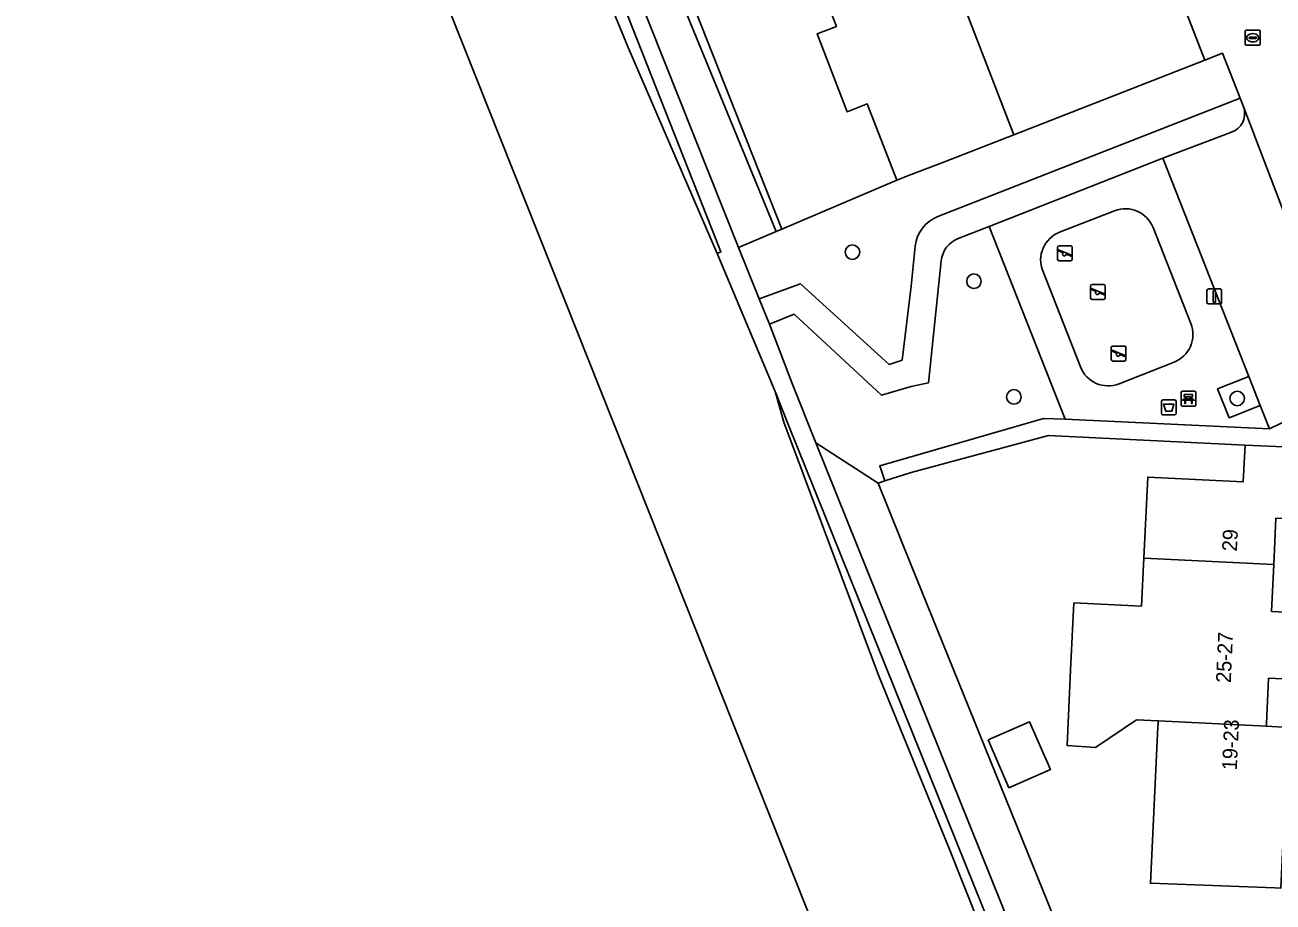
# Model space of a CAD drawing. Extents: x 158472 to 159562, y 388525 to 389606.
# Drawn here: x 158940.4 to 159024.3, y 388560.1 to 388619.1 of the extents above; entities that cross this region are included whole.
import ezdxf

# ---------------------------------------------------------------- set-up
doc = ezdxf.new("R2010")
doc.units = 0
for name, color, linetype in [('IMGEO_Afvalbak', 7, 'Continuous'), ('IMGEO_Bank', 7, 'Continuous'), ('IMGEO_Boom', 7, 'Continuous'), ('IMGEO_Erf', 7, 'Continuous'), ('IMGEO_Grasland_overig', 7, 'Continuous'), ('IMGEO_Groenvoorziening', 7, 'Continuous'), ('IMGEO_Hek', 7, 'Continuous'), ('IMGEO_Kolk', 7, 'Continuous'), ('IMGEO_Lichtmast', 7, 'Continuous'), ('IMGEO_Meer_plas_ven_vijver', 7, 'Continuous'), ('IMGEO_Oever', 7, 'Continuous'), ('IMGEO_Pand', 7, 'Continuous'), ('IMGEO_Pand_nummerreeks', 7, 'Continuous'), ('IMGEO_Parkeervlak_open', 7, 'Continuous'), ('IMGEO_Rijbaan_lokaal_open', 7, 'Continuous'), ('IMGEO_Speelvoorziening', 7, 'Continuous'), ('IMGEO_Terreindeel_zand', 7, 'Continuous'), ('IMGEO_Voetpad_halfverhard', 7, 'Continuous'), ('IMGEO_Voetpad_open', 7, 'Continuous'), ('IMGEO_Walbescherming', 7, 'Continuous')]:
    doc.layers.add(name, color=color, linetype=linetype)

msp = doc.modelspace()

# ---------------------------------------------------------------- linework, layer by layer
at = {"layer": 'IMGEO_Afvalbak'}
for p, q in [((159016.827, 388592.973), (159016.827, 388593.773)), ((159016.827, 388593.773), (159016.827, 388592.973)), ((159016.927, 388593.873), (159017.717, 388593.873)), ((159017.717, 388593.873), (159016.927, 388593.873)), ((159017.817, 388593.773), (159017.817, 388592.973)), ((159017.817, 388592.973), (159017.817, 388593.773)), ((159017.717, 388592.873), (159016.927, 388592.873)), ((159016.927, 388592.873), (159017.717, 388592.873))]:
    msp.add_line(p, q, dxfattribs=at)
msp.add_lwpolyline([(159016.97, 388593.587), (159017.674, 388593.587), (159017.525, 388593.117), (159017.119, 388593.117), (159016.97, 388593.587)], dxfattribs=at)
for centre, start, end in [((159016.927, 388593.773), 90, 180), ((159016.927, 388593.773), 90, 180), ((159017.717, 388593.773), 0, 90), ((159017.717, 388593.773), 360, 90), ((159016.927, 388592.973), 180, 270), ((159016.927, 388592.973), 180, 270), ((159017.717, 388592.973), 270, 0), ((159017.717, 388592.973), 270, 0)]:
    msp.add_arc(centre, 0.1, start, end, dxfattribs=at)
at = {"layer": 'IMGEO_Bank'}
for p, q in [((159018.147, 388593.529), (159018.147, 388594.37)), ((159018.147, 388594.37), (159018.147, 388593.529)), ((159018.222, 388594.454), (159019.063, 388594.454)), ((159019.063, 388594.454), (159018.222, 388594.454)), ((159018.456, 388593.96), (159018.456, 388594.066)), ((159018.5, 388594.066), (159018.5, 388593.96)), ((159018.788, 388594.072), (159018.506, 388594.072)), ((159018.506, 388593.954), (159018.788, 388593.954)), ((159018.794, 388593.96), (159018.794, 388594.066)), ((159018.838, 388594.066), (159018.838, 388593.96)), ((159019.147, 388594.379), (159019.147, 388593.538)), ((159019.147, 388593.538), (159019.147, 388594.379)), ((159019.072, 388593.454), (159018.231, 388593.454)), ((159018.231, 388593.454), (159019.072, 388593.454)), ((159018.844, 388593.852), (159018.451, 388593.852))]:
    msp.add_line(p, q, dxfattribs=at)
for points in [[(159018.394, 388593.852), (159018.252, 388593.852), (159018.364, 388593.954), (159018.45, 388593.954)], [(159018.45, 388594.072), (159018.364, 388594.072), (159018.364, 388594.233), (159018.927, 388594.233), (159018.927, 388594.072), (159018.844, 388594.072)], [(159018.844, 388593.954), (159018.927, 388593.954), (159019.039, 388593.852), (159018.9, 388593.852)], [(159018.444, 388593.845), (159018.444, 388593.638), (159018.401, 388593.638), (159018.401, 388593.845)], [(159018.894, 388593.845), (159018.894, 388593.638), (159018.85, 388593.638), (159018.85, 388593.845)]]:
    msp.add_lwpolyline(points, dxfattribs=at)
for centre, radius, start, end in [((159018.225, 388594.376), 0.0779, 92.4484, 184.28452), ((159018.225, 388594.376), 0.0779, 92.4484, 184.28452), ((159018.449, 388594.065), 0.00671, 2.89567, 87.10433), ((159018.449, 388593.961), 0.00671, 272.89567, 357.10433), ((159018.506, 388594.065), 0.00671, 92.89567, 177.10433), ((159018.506, 388593.961), 0.00671, 182.89567, 267.10433), ((159018.788, 388594.065), 0.00671, 2.89567, 87.10433), ((159018.788, 388593.961), 0.00671, 272.89567, 357.10433), ((159018.845, 388594.065), 0.00671, 92.89567, 177.10433), ((159018.845, 388593.961), 0.00671, 182.89567, 267.10433), ((159019.069, 388594.376), 0.0779, 2.4484, 94.28452), ((159019.069, 388594.376), 0.0779, 2.4484, 94.28452), ((159018.225, 388593.532), 0.0779, 182.4484, 274.28452), ((159018.225, 388593.532), 0.0779, 182.4484, 274.28452), ((159018.394, 388593.845), 0.00671, 2.89567, 87.10433), ((159018.451, 388593.845), 0.00671, 92.89567, 177.10433), ((159018.843, 388593.845), 0.00671, 2.89567, 87.10433), ((159018.9, 388593.845), 0.00671, 92.89567, 177.10433), ((159019.069, 388593.532), 0.0779, 272.4484, 4.28452), ((159019.069, 388593.532), 0.0779, 272.4484, 4.28452)]:
    msp.add_arc(centre, radius, start, end, dxfattribs=at)
at = {"layer": 'IMGEO_Boom'}
for centre in [(158996.045, 388603.807), (159004.217, 388601.849), (159006.905, 388594.075), (159021.925, 388593.97)]:
    msp.add_circle(centre, 0.489, dxfattribs=at)
at = {"layer": 'IMGEO_Erf'}
for points in [[(158957.964, 388689.565), (158991.293, 388605.352), (158999.029, 388608.643), (158997.043, 388613.774), (158995.686, 388613.249), (158993.663, 388618.477), (158994.969, 388618.982), (158991.07, 388629.056)], [(159024.462, 388561.08), (159016.089, 388561.387), (159016.597, 388571.909), (159016.608, 388572.139), (159016.616, 388572.297), (159015.145, 388572.37), (159012.383, 388570.509), (159010.479, 388570.654), (159010.723, 388575.711), (159010.941, 388580.234), (159015.494, 388580.014), (159015.65, 388583.238), (159015.913, 388588.687), (159022.337, 388588.377), (159022.456, 388590.843), (159009.225, 388591.48), (159000, 388588.992), (158998.228, 388588.425), (158997.772, 388588.279), (159000, 388582.772), (159013.109, 388550.405)], [(159030.147, 388590.079), (159030.021, 388590.479), (159027.022, 388590.623), (159026.791, 388585.828), (159024.536, 388585.936), (159024.386, 388582.821), (159024.233, 388579.656), (159029.39, 388579.407), (159029.173, 388574.92), (159024.038, 388575.168), (159023.89, 388572.105), (159023.882, 388571.935), (159025.383, 388571.86), (159025.206, 388568.195), (159030.493, 388567.94), (159036.047, 388567.672), (159036.701, 388583.22), (159035.299, 388583.862)]]:
    msp.add_lwpolyline(points, dxfattribs=at)
for points in [[(159019.743, 388616.716), (159016.062, 388626.181), (159013.165, 388624.999), (159011.969, 388628.086), (159002.047, 388624.245), (159006.906, 388611.691)], [(159005.166, 388571.023), (159007.965, 388572.241), (159009.363, 388569.028), (159006.564, 388567.809)]]:
    msp.add_lwpolyline(points, close=True, dxfattribs=at)
at = {"layer": 'IMGEO_Grasland_overig'}
msp.add_lwpolyline([(158991.293, 388605.352), (158957.964, 388689.565), (158956.571, 388688.996), (158955.214, 388688.441), (158955.178, 388688.038), (158955.022, 388686.321), (158956.851, 388684.593), (158960.645, 388678.761), (158990.911, 388605.19)], close=True, dxfattribs=at)
at = {"layer": 'IMGEO_Groenvoorziening'}
for points in [[(158964.429, 388664.228), (158988.389, 388604.118), (158990.911, 388605.19), (158960.645, 388678.761)], [(159019.743, 388616.716), (159006.906, 388611.691)], [(159020.93, 388617.172), (159019.743, 388616.716)], [(159022.119, 388614.156), (159020.93, 388617.172)], [(159001.783, 388606.194), (159022.119, 388614.156)], [(159006.906, 388611.691), (159002.243, 388609.887)], [(159002.243, 388609.887), (159000, 388609.019), (158999.029, 388608.643)], [(158999.029, 388608.643), (158991.293, 388605.352)], [(158990.911, 388605.19), (158988.389, 388604.118)], [(159002.022, 388603.231), (159001.164, 388595.031), (159000, 388594.769), (158998.008, 388594.191), (158992.129, 388599.643), (158990.46, 388598.969), (158991.982, 388594.983), (158993.589, 388590.993), (158997.772, 388588.279), (158998.228, 388588.425), (158997.882, 388589.442), (159008.885, 388592.619), (159010.362, 388592.573), (159005.251, 388605.541)], [(158991.293, 388605.352), (158990.911, 388605.19)], [(159005.251, 388605.541), (159003.156, 388604.72)], [(158988.389, 388604.118), (158989.761, 388600.676)], [(159000, 388601.513), (159000.271, 388604.209)], [(158989.761, 388600.676), (158992.549, 388601.673), (158998.506, 388596.258), (158999.384, 388596.544), (159000, 388601.513)], [(159019.02, 388530.138), (159019.207, 388530.214), (159018.596, 388531.721), (159019.351, 388532.038), (159017.294, 388533.727), (159015.664, 388535.517), (159013.987, 388537.691), (159012.538, 388540.636), (158991.75, 388592.186), (158990.839, 388594.444), (158991.438, 388592.388), (158997.787, 388575.374), (159002.555, 388563.716), (159010.129, 388544.708), (159010.915, 388542.723), (159014.7, 388535.704), (159016.973, 388533.673), (159018.271, 388532.213), (159019.02, 388530.138)]]:
    msp.add_lwpolyline(points, dxfattribs=at)
for points in [[(159022.698, 388595.459), (159020.611, 388594.626), (159021.388, 388592.677), (159023.471, 388593.498)], [(159000, 388582.772), (158997.772, 388588.279), (158993.589, 388590.993), (159013.648, 388541.179), (159015.143, 388538.144), (159017.045, 388535.834), (159019.242, 388533.931), (159020.362, 388532.463), (159013.79, 388548.723), (159013.109, 388550.405)]]:
    msp.add_lwpolyline(points, close=True, dxfattribs=at)
for centre, radius, start, end in [((159002.657, 388603.96), 2.399, 111.36942, 174.0366), ((159003.813, 388603.044), 1.801, 111.39225, 174.02304)]:
    msp.add_arc(centre, radius, start, end, dxfattribs=at)
at = {"layer": 'IMGEO_Hek'}
msp.add_lwpolyline([(158955.178, 388688.038), (158955.022, 388686.321), (158956.851, 388684.593), (158960.645, 388678.761), (158990.911, 388605.19)], dxfattribs=at)
at = {"layer": 'IMGEO_Kolk'}
for p, q in [((159022.471, 388617.792), (159022.471, 388618.644)), ((159022.546, 388618.718), (159023.398, 388618.718)), ((159022.773, 388618.261), (159023.171, 388618.261)), ((159022.959, 388618.498), (159022.984, 388618.498)), ((159023.472, 388618.644), (159023.472, 388617.792)), ((159023.398, 388617.718), (159022.546, 388617.718)), ((159022.73, 388618.212), (159022.73, 388618.224)), ((159023.168, 388618.175), (159022.77, 388618.175)), ((159022.982, 388617.938), (159022.957, 388617.938)), ((159023.214, 388618.224), (159023.214, 388618.212))]:
    msp.add_line(p, q, dxfattribs=at)
for points in [[(159022.471, 388617.792), (159022.471, 388618.644)], [(159022.546, 388618.718), (159023.398, 388618.718)], [(159023.472, 388618.644), (159023.472, 388617.792)], [(159023.398, 388617.718), (159022.546, 388617.718)]]:
    msp.add_lwpolyline(points, dxfattribs=at)
for centre, radius, start, end in [((159022.548, 388618.642), 0.0765, 91.55205, 178.44795), ((159022.548, 388618.642), 0.0765, 91.55205, 178.44795), ((159022.77, 388618.221), 0.0403, 85.87752, 175.75265), ((159023.175, 388618.223), 0.0386, 1.73085, 96.63898), ((159023.396, 388618.642), 0.0765, 1.55205, 88.44795), ((159023.396, 388618.642), 0.0765, 1.55205, 88.44795), ((159022.548, 388617.794), 0.0765, 181.55205, 268.44795), ((159022.548, 388617.794), 0.0765, 181.55205, 268.44795), ((159022.767, 388618.211), 0.0366, 178.93798, 274.71019), ((159023.171, 388618.218), 0.043, 264.86636, 352.45326), ((159023.396, 388617.794), 0.0765, 271.55205, 358.44795), ((159023.396, 388617.794), 0.0765, 271.55205, 358.44795)]:
    msp.add_arc(centre, radius, start, end, dxfattribs=at)
for centre, major_axis, ratio, start_param, end_param in [((159022.958, 388618.218), (-0.387, 0.002), 0.722429, 4.712389, 7.853982), ((159022.983, 388618.218), (-0.39, 0.002), 0.717154, 1.570796, 4.712389)]:
    msp.add_ellipse(centre, major_axis=major_axis, ratio=ratio, start_param=start_param, end_param=end_param, dxfattribs=at)
at = {"layer": 'IMGEO_Lichtmast'}
for p, q in [((159019.89, 388600.43), (159019.89, 388601.23)), ((159019.89, 388601.23), (159019.89, 388600.43)), ((159019.99, 388601.33), (159020.78, 388601.33)), ((159020.78, 388601.33), (159019.99, 388601.33)), ((159020.88, 388601.23), (159020.88, 388600.43)), ((159020.88, 388600.43), (159020.88, 388601.23)), ((159020.78, 388600.33), (159019.99, 388600.33)), ((159019.99, 388600.33), (159020.78, 388600.33))]:
    msp.add_line(p, q, dxfattribs=at)
msp.add_lwpolyline([(159020.31, 388601.205), (159020.46, 388601.205), (159020.46, 388600.455), (159020.31, 388600.455), (159020.31, 388601.205)], dxfattribs=at)
for centre, start, end in [((159019.99, 388601.23), 90, 180), ((159019.99, 388601.23), 90, 180), ((159020.78, 388601.23), 0, 90), ((159020.78, 388601.23), 360, 90), ((159019.99, 388600.43), 180, 270), ((159019.99, 388600.43), 180, 270), ((159020.78, 388600.43), 270, 0), ((159020.78, 388600.43), 270, 0)]:
    msp.add_arc(centre, 0.1, start, end, dxfattribs=at)
at = {"layer": 'IMGEO_Meer_plas_ven_vijver'}
for points in [[(158822.445, 388708.992), (158897.018, 388691.315), (158945.096, 388679.918), (158977.475, 388598.587), (159006.711, 388525.15)], [(159006.711, 388525.15), (159016.465, 388529.103), (159015.89, 388530.625), (159014.648, 388533.301), (159010.915, 388542.723), (159010.129, 388544.708), (159002.555, 388563.716), (158997.787, 388575.374), (158991.438, 388592.388), (158990.839, 388594.444), (158986.94, 388603.708), (158980.947, 388617.566), (158968.458, 388647.949)]]:
    msp.add_lwpolyline(points, dxfattribs=at)
at = {"layer": 'IMGEO_Oever'}
msp.add_lwpolyline([(158827.937, 388714.025), (158857.904, 388707.552), (158870.659, 388705.032), (158890.03, 388700.878), (158930.531, 388691.605), (158933.78, 388690.674), (158936.537, 388689.763), (158939.152, 388688.776), (158942.359, 388686.96), (158946.034, 388684.462), (158946.319, 388684.258), (158947.44, 388683.422), (158950.566, 388680.786), (158953.445, 388677.881), (158956.052, 388674.731), (158958.368, 388671.444), (158960.512, 388667.76), (158962.318, 388663.898), (158964.408, 388658.159), (158968.458, 388647.949), (158980.947, 388617.566), (158986.94, 388603.708), (158987.193, 388603.818), (158963.842, 388663.007)], dxfattribs=at)
at = {"layer": 'IMGEO_Pand'}
for points in [[(159006.906, 388611.691), (159002.047, 388624.245), (159011.969, 388628.086), (159008.885, 388636.053), (159003.831, 388634.097), (159003.305, 388635.455), (159000, 388634.176), (158998.643, 388633.65), (158997.95, 388633.382), (158998.51, 388631.936), (158991.07, 388629.056), (158994.969, 388618.982), (158993.663, 388618.477), (158995.686, 388613.249), (158997.043, 388613.774), (158999.029, 388608.643), (159000, 388609.019), (159002.243, 388609.887)], [(159027.022, 388590.623), (159024.037, 388590.767), (159022.456, 388590.843), (159022.337, 388588.377), (159015.913, 388588.687), (159015.65, 388583.238), (159024.386, 388582.821), (159024.536, 388585.936), (159026.791, 388585.828)], [(159024.386, 388582.821), (159015.65, 388583.238), (159015.494, 388580.014), (159010.941, 388580.234), (159010.723, 388575.711), (159010.479, 388570.654), (159012.383, 388570.509), (159015.145, 388572.37), (159016.616, 388572.297), (159023.882, 388571.935), (159023.89, 388572.105), (159024.038, 388575.168), (159029.173, 388574.92), (159029.39, 388579.407), (159024.233, 388579.656)], [(159005.166, 388571.023), (159006.564, 388567.809), (159009.363, 388569.028), (159007.965, 388572.241)], [(159025.206, 388568.195), (159025.383, 388571.86), (159023.882, 388571.935), (159016.616, 388572.297), (159016.608, 388572.139), (159016.597, 388571.909), (159016.089, 388561.387), (159024.462, 388561.08), (159024.862, 388561.065)]]:
    msp.add_lwpolyline(points, close=True, dxfattribs=at)
at = {"layer": 'IMGEO_Parkeervlak_open'}
for points in [[(159029.986, 388593.603), (159030.018, 388593.527), (159022.386, 388613.46)], [(159021.549, 388611.879), (159016.922, 388610.114), (159022.698, 388595.459), (159023.471, 388593.498), (159024.088, 388591.933), (159028.794, 388594.2)]]:
    msp.add_lwpolyline(points, dxfattribs=at)
msp.add_arc((159021.117, 388613.12), 1.314, 289.20787, 14.99758, dxfattribs=at)
at = {"layer": 'IMGEO_Rijbaan_lokaal_open'}
msp.add_lwpolyline([(159016.062, 388626.181), (159019.743, 388616.716), (159020.93, 388617.172), (159022.119, 388614.156), (159022.386, 388613.46), (159030.018, 388593.527)], dxfattribs=at)
at = {"layer": 'IMGEO_Speelvoorziening'}
for p, q in [((159009.84, 388603.328), (159009.84, 388604.128)), ((159009.84, 388604.128), (159009.84, 388603.328)), ((159009.94, 388604.228), (159010.73, 388604.228)), ((159010.73, 388604.228), (159009.94, 388604.228)), ((159010.83, 388604.128), (159010.83, 388603.328)), ((159010.83, 388603.328), (159010.83, 388604.128)), ((159010.223, 388603.756), (159009.884, 388603.893)), ((159009.909, 388603.953), (159010.785, 388603.6)), ((159010.73, 388603.228), (159009.94, 388603.228)), ((159009.94, 388603.228), (159010.73, 388603.228)), ((159010.761, 388603.54), (159010.421, 388603.677)), ((159012.059, 388600.729), (159012.059, 388601.529)), ((159012.059, 388601.529), (159012.059, 388600.729)), ((159012.159, 388601.629), (159012.949, 388601.629)), ((159012.949, 388601.629), (159012.159, 388601.629)), ((159013.049, 388601.529), (159013.049, 388600.729)), ((159013.049, 388600.729), (159013.049, 388601.529)), ((159012.442, 388601.157), (159012.103, 388601.294)), ((159012.128, 388601.354), (159013.004, 388601.001)), ((159012.949, 388600.629), (159012.159, 388600.629)), ((159012.159, 388600.629), (159012.949, 388600.629)), ((159012.98, 388600.941), (159012.64, 388601.078)), ((159013.453, 388596.587), (159013.453, 388597.387)), ((159013.453, 388597.387), (159013.453, 388596.587)), ((159013.553, 388597.487), (159014.343, 388597.487)), ((159014.343, 388597.487), (159013.553, 388597.487)), ((159014.443, 388597.387), (159014.443, 388596.587)), ((159014.443, 388596.587), (159014.443, 388597.387)), ((159013.836, 388597.015), (159013.497, 388597.152)), ((159013.522, 388597.212), (159014.398, 388596.859)), ((159014.343, 388596.487), (159013.553, 388596.487)), ((159013.553, 388596.487), (159014.343, 388596.487)), ((159014.374, 388596.799), (159014.034, 388596.936))]:
    msp.add_line(p, q, dxfattribs=at)
for centre, radius, start, end in [((159009.94, 388604.128), 0.1, 90, 180), ((159009.94, 388604.128), 0.1, 90, 180), ((159010.73, 388604.128), 0.1, 0, 90), ((159010.73, 388604.128), 0.1, 360, 90), ((159009.94, 388603.328), 0.1, 180, 270), ((159009.94, 388603.328), 0.1, 180, 270), ((159009.897, 388603.923), 0.0327, 68.07798, 248.07798), ((159010.302, 388603.666), 0.12, 130.99278, 5.16318), ((159010.73, 388603.328), 0.1, 270, 0), ((159010.73, 388603.328), 0.1, 270, 0), ((159010.773, 388603.57), 0.0327, 248.07798, 68.07798), ((159012.159, 388601.529), 0.1, 90, 180), ((159012.159, 388601.529), 0.1, 90, 180), ((159012.949, 388601.529), 0.1, 0, 90), ((159012.949, 388601.529), 0.1, 360, 90), ((159012.159, 388600.729), 0.1, 180, 270), ((159012.159, 388600.729), 0.1, 180, 270), ((159012.116, 388601.324), 0.0327, 68.07798, 248.07798), ((159012.521, 388601.067), 0.12, 130.99278, 5.16318), ((159012.949, 388600.729), 0.1, 270, 0), ((159012.949, 388600.729), 0.1, 270, 0), ((159012.992, 388600.971), 0.0327, 248.07798, 68.07798), ((159013.553, 388597.387), 0.1, 90, 180), ((159013.553, 388597.387), 0.1, 90, 180), ((159014.343, 388597.387), 0.1, 0, 90), ((159014.343, 388597.387), 0.1, 360, 90), ((159013.553, 388596.587), 0.1, 180, 270), ((159013.553, 388596.587), 0.1, 180, 270), ((159013.51, 388597.182), 0.0327, 68.07798, 248.07798), ((159013.915, 388596.925), 0.12, 130.99278, 5.16318), ((159014.343, 388596.587), 0.1, 270, 0), ((159014.343, 388596.587), 0.1, 270, 0), ((159014.386, 388596.829), 0.0327, 248.07798, 68.07798)]:
    msp.add_arc(centre, radius, start, end, dxfattribs=at)
at = {"layer": 'IMGEO_Terreindeel_zand'}
for points in [[(159013.676, 388606.589), (159009.973, 388605.139)], [(159018.81, 388599.005), (159016.266, 388605.46)], [(159008.841, 388602.543), (159011.385, 388596.089)], [(159013.975, 388594.96), (159017.678, 388596.41)]]:
    msp.add_lwpolyline(points, dxfattribs=at)
for centre, radius, start, end in [((159014.404, 388604.723), 2.003, 21.59113, 111.30339), ((159010.7, 388603.277), 1.999, 111.33931, 201.54094), ((159016.948, 388598.273), 2.001, 291.39519, 21.46889), ((159013.246, 388596.822), 2, 201.49992, 291.3946)]:
    msp.add_arc(centre, radius, start, end, dxfattribs=at)
at = {"layer": 'IMGEO_Voetpad_halfverhard'}
for points in [[(158990.46, 388598.969), (158989.761, 388600.676), (158988.389, 388604.118), (158964.429, 388664.228)], [(158963.842, 388663.007), (158987.193, 388603.818), (158986.94, 388603.708), (158990.839, 388594.444), (158991.75, 388592.186), (159012.538, 388540.636), (159013.987, 388537.691), (159015.664, 388535.517), (159017.294, 388533.727), (159019.351, 388532.038), (159020.362, 388532.463), (159019.242, 388533.931), (159017.045, 388535.834), (159015.143, 388538.144), (159013.648, 388541.179), (158993.589, 388590.993), (158991.982, 388594.983), (158990.46, 388598.969)], [(159022.386, 388613.46), (159022.119, 388614.156), (159001.783, 388606.194)], [(159003.156, 388604.72), (159005.251, 388605.541), (159016.922, 388610.114), (159021.549, 388611.879)], [(159000.271, 388604.209), (159000, 388601.513), (158999.384, 388596.544), (158998.506, 388596.258), (158992.549, 388601.673), (158989.761, 388600.676), (158990.46, 388598.969), (158992.129, 388599.643), (158998.008, 388594.191), (159000, 388594.769)], [(159000, 388594.769), (159001.164, 388595.031), (159002.022, 388603.231)]]:
    msp.add_lwpolyline(points, dxfattribs=at)
for centre, radius, start, end in [((159021.117, 388613.12), 1.314, 289.20787, 14.99758), ((159002.657, 388603.96), 2.399, 111.36942, 174.0366), ((159003.813, 388603.044), 1.801, 111.39225, 174.02304)]:
    msp.add_arc(centre, radius, start, end, dxfattribs=at)
at = {"layer": 'IMGEO_Voetpad_open'}
msp.add_lwpolyline([(159022.698, 388595.459), (159016.922, 388610.114), (159005.251, 388605.541), (159010.362, 388592.573), (159024.088, 388591.933), (159023.471, 388593.498), (159021.388, 388592.677), (159020.611, 388594.626)], close=True, dxfattribs=at)
for points in [[(159009.973, 388605.139), (159013.676, 388606.589)], [(159016.266, 388605.46), (159018.81, 388599.005)], [(159011.385, 388596.089), (159008.841, 388602.543)], [(159017.678, 388596.41), (159013.975, 388594.96)], [(159028.794, 388594.2), (159024.088, 388591.933), (159010.362, 388592.573), (159008.885, 388592.619), (158997.882, 388589.442), (158998.228, 388588.425), (159000, 388588.992), (159009.225, 388591.48), (159022.456, 388590.843), (159024.037, 388590.767), (159027.022, 388590.623), (159030.021, 388590.479), (159030.147, 388590.079)]]:
    msp.add_lwpolyline(points, dxfattribs=at)
for centre, radius, start, end in [((159014.404, 388604.723), 2.003, 21.59113, 111.30339), ((159010.7, 388603.277), 1.999, 111.33931, 201.54094), ((159016.948, 388598.273), 2.001, 291.39519, 21.46889), ((159013.246, 388596.822), 2, 201.49992, 291.3946)]:
    msp.add_arc(centre, radius, start, end, dxfattribs=at)
at = {"layer": 'IMGEO_Walbescherming'}
msp.add_lwpolyline([(159002.555, 388563.716), (158997.787, 388575.374)], dxfattribs=at)

# ---------------------------------------------------------------- texts
at = {"layer": 'IMGEO_Pand_nummerreeks'}
for s, rotation, p in [('29', 87.24428, (159021.904, 388583.674)), ('25-27', 87.34742, (159021.493, 388574.837)), ('19-23', 87.38752, (159021.899, 388568.962))]:
    msp.add_text(s, height=1, rotation=rotation, dxfattribs=at).set_placement(p)

doc.saveas('drawing.dxf')
